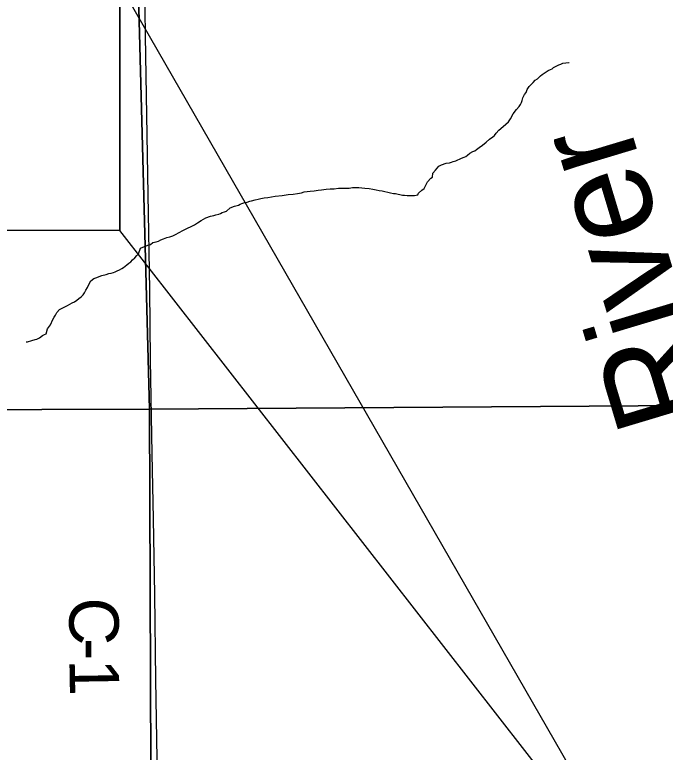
# Model space of a CAD drawing. Extents: x 10.6 to 44.6, y -2.6 to 23.4.
# Drawn here: x 16.111 to 16.858, y 18.4 to 19.247 of the extents above; entities that cross this region are included whole.
import ezdxf

# ---------------------------------------------------------------- set-up
doc = ezdxf.new("R2010")
doc.units = 0
for name, color, linetype in [('GM_X_County_Road', 7, 'Continuous'), ('GM_X_County_Road_Text', 7, 'Continuous'), ('GM_X_Major_River_Text', 7, 'Continuous'), ('GM_X_Minor_River', 7, 'Continuous'), ('GM_X_Section', 7, 'Continuous'), ('SH_Border', 7, 'Continuous')]:
    doc.layers.add(name, color=color, linetype=linetype)

msp = doc.modelspace()

# ---------------------------------------------------------------- linework, layer by layer
at = {"layer": 'GM_X_County_Road'}
msp.add_lwpolyline([(16.25938, 19.313), (16.26077, 19.22311), (16.26377, 19.0408), (16.26562, 18.93128), (16.26655, 18.85087), (16.2684, 18.74297), (16.26978, 18.66833), (16.27117, 18.58122), (16.27232, 18.48325), (16.27394, 18.39268), (16.27533, 18.32036), (16.27579, 18.23325), (16.27625, 18.19859)], dxfattribs=at)
at = {"layer": 'GM_X_Minor_River'}
for points in [[(16.4435, 19.04373), (16.44692, 19.04419), (16.45033, 19.04464), (16.45488, 19.04512), (16.45943, 19.04598), (16.46324, 19.04606), (16.46854, 19.04694), (16.47309, 19.04742), (16.47766, 19.04751), (16.48259, 19.048), (16.48716, 19.0481), (16.49096, 19.04818), (16.49514, 19.04827), (16.49894, 19.04874), (16.50274, 19.04882), (16.50616, 19.04889), (16.50959, 19.04859), (16.51302, 19.04828), (16.51798, 19.04763), (16.52218, 19.04696), (16.526, 19.04629), (16.52943, 19.0456), (16.53287, 19.04491), (16.53593, 19.04422), (16.53937, 19.04353), (16.54243, 19.04284), (16.54587, 19.04216), (16.54815, 19.04183), (16.55618, 19.0401), (16.55846, 19.04015), (16.56151, 19.03984), (16.56456, 19.03952), (16.56684, 19.03957), (16.56988, 19.03964), (16.57405, 19.04049), (16.57477, 19.0424), (16.5785, 19.04591), (16.58112, 19.04786), (16.58514, 19.05555), (16.58886, 19.05943), (16.59074, 19.06061), (16.59102, 19.06518), (16.59437, 19.06867), (16.59808, 19.07331), (16.60109, 19.0749), (16.60637, 19.07691), (16.61016, 19.07738), (16.61244, 19.07781), (16.61432, 19.07861), (16.61773, 19.07944), (16.62413, 19.08262), (16.62714, 19.08383), (16.62903, 19.08463), (16.6309, 19.08619), (16.63351, 19.08852), (16.63728, 19.09013), (16.63955, 19.09094), (16.64141, 19.0925), (16.64441, 19.09484), (16.64816, 19.09758), (16.65226, 19.10109), (16.65638, 19.1046), (16.66013, 19.10696), (16.662, 19.10852), (16.66384, 19.11123), (16.66681, 19.11471), (16.67205, 19.119), (16.67503, 19.12173), (16.67802, 19.12445), (16.68022, 19.12792), (16.68352, 19.13369), (16.68723, 19.13834), (16.6902, 19.14182), (16.69167, 19.14413), (16.69315, 19.14644), (16.69386, 19.14874), (16.69455, 19.1518), (16.69637, 19.15564), (16.69823, 19.15795), (16.69967, 19.16141), (16.70188, 19.16488), (16.70449, 19.16759), (16.70635, 19.16953), (16.70857, 19.17224), (16.7112, 19.17382), (16.71493, 19.17732), (16.7168, 19.17888), (16.71906, 19.18007), (16.72131, 19.18164), (16.72356, 19.18321), (16.72619, 19.18441), (16.72808, 19.1852), (16.72995, 19.18677), (16.73296, 19.18835), (16.73597, 19.18994), (16.73823, 19.19075), (16.7405, 19.19156), (16.74732, 19.19246), (16.7477, 19.19247)], [(16.12383, 18.87146), (16.12535, 18.87149), (16.13026, 18.87312), (16.13442, 18.87435), (16.13631, 18.87477), (16.13932, 18.87636), (16.14269, 18.87871), (16.14495, 18.8799), (16.14684, 18.8807), (16.14824, 18.88644), (16.15194, 18.89108), (16.15447, 18.89721), (16.15594, 18.8999), (16.15779, 18.90222), (16.15924, 18.9053), (16.16221, 18.90878), (16.16447, 18.90997), (16.17125, 18.91316), (16.17426, 18.91474), (16.17689, 18.91632), (16.17953, 18.91752), (16.18215, 18.91948), (16.18439, 18.92143), (16.18701, 18.92338), (16.18924, 18.92571), (16.1911, 18.92803), (16.19255, 18.9311), (16.19439, 18.93418), (16.19584, 18.93764), (16.19804, 18.94148), (16.20178, 18.94423), (16.20518, 18.94544), (16.20782, 18.94664), (16.21084, 18.94784), (16.21575, 18.94909), (16.21878, 18.94992), (16.22143, 18.95035), (16.22408, 18.95117), (16.22634, 18.95198), (16.2286, 18.95317), (16.23124, 18.95437), (16.23387, 18.95595), (16.23574, 18.95713), (16.23949, 18.95987), (16.24173, 18.96182), (16.24398, 18.96339), (16.24621, 18.96571), (16.24883, 18.96805), (16.25105, 18.97076), (16.25291, 18.9727), (16.25544, 18.97922), (16.26373, 18.98282), (16.26676, 18.98326), (16.26938, 18.9856), (16.27316, 18.98644), (16.27581, 18.98726), (16.27882, 18.98885), (16.28183, 18.99005), (16.28561, 18.99127), (16.28902, 18.99211), (16.29241, 18.99332), (16.29542, 18.99491), (16.29956, 18.99728), (16.30407, 18.99966), (16.30935, 19.00205), (16.31349, 19.00404), (16.31725, 19.00602), (16.32063, 19.00838), (16.32513, 19.01113), (16.3304, 19.01391), (16.33568, 19.01592), (16.33947, 19.01677), (16.34173, 19.01758), (16.34514, 19.01841), (16.34702, 19.01921), (16.34929, 19.02002), (16.35193, 19.02084), (16.3542, 19.02165), (16.3583, 19.02554), (16.3632, 19.02754), (16.36774, 19.02878), (16.36963, 19.02958), (16.37151, 19.03038), (16.37416, 19.0312), (16.37605, 19.03162), (16.37794, 19.03205), (16.38096, 19.03325), (16.38285, 19.03367), (16.38701, 19.0349), (16.39042, 19.03536), (16.39345, 19.03618), (16.39724, 19.03703), (16.40141, 19.0375), (16.40597, 19.03798), (16.41013, 19.03883), (16.4181, 19.03976), (16.42493, 19.04067), (16.43062, 19.04117), (16.43555, 19.04204), (16.4401, 19.0429), (16.4435, 19.04373)]]:
    msp.add_lwpolyline(points, dxfattribs=at)
at = {"layer": 'GM_X_Section'}
for points in [[(16.23849, 19.81579), (17.1955, 19.83846), (17.21979, 18.8008), (16.26575, 18.79438)], [(16.26575, 18.79438), (17.21979, 18.8008), (17.2448, 17.67043), (16.26964, 17.66059)], [(15.27514, 18.79123), (16.26575, 18.79438), (16.26964, 17.66059), (15.28017, 17.65049)]]:
    msp.add_lwpolyline(points, close=True, dxfattribs=at)
msp.add_lwpolyline([(15.27378, 19.56461), (15.27309, 19.80416), (16.23849, 19.81579), (16.26575, 18.79438), (15.27514, 18.79123), (15.27492, 18.99958)], dxfattribs=at)
at = {"layer": 'SH_Border'}
for points in [[(14.50601, 19.56461), (16.23136, 19.56461), (16.23136, 18.99958), (14.50601, 18.99958)], [(16.23136, 19.2821), (16.85207, 18.20298), (16.23136, 18.99958)]]:
    msp.add_lwpolyline(points, close=True, dxfattribs=at)

# ---------------------------------------------------------------- texts
at = {"layer": 'GM_X_County_Road_Text'}
for s, rotation, p in [('C', 270.01172, (16.17345, 18.57789)), ('-', 270.15445, (16.17346, 18.53107)), ('1', 271.00144, (16.17353, 18.50682))]:
    msp.add_text(s, height=0.05682, rotation=rotation, dxfattribs=at).set_placement(p)
at = {"layer": 'GM_X_Major_River_Text'}
msp.add_text('River', height=0.113712, rotation=106.75134, dxfattribs=at).set_placement((16.91617, 18.79205))

doc.saveas('drawing.dxf')
